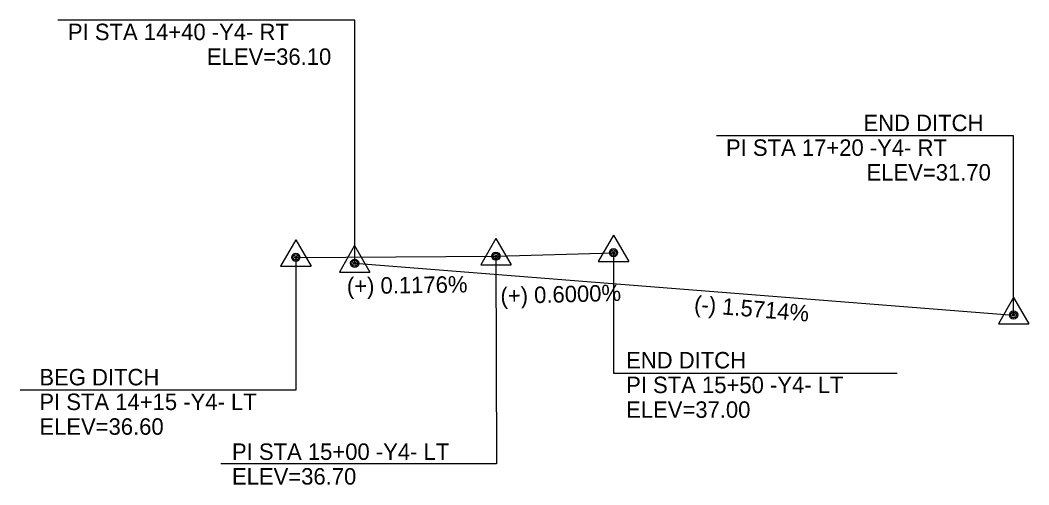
# Model space of a CAD drawing. Extents: x 2179808 to 2190174, y 63168 to 78602.
# Drawn here: x 2186905.5 to 2187334.2, y 75243.6 to 75441.1 of the extents above; entities that cross this region are included whole.
import ezdxf

# ---------------------------------------------------------------- set-up
doc = ezdxf.new("R2010")
doc.units = 0
for name, color, linetype in [('Default', 7, 'Continuous'), ('Prop Vertical Profile Ditch Grade Left', 7, 'Continuous'), ('Prop Vertical Profile Ditch Grade Left Label', 7, 'Continuous'), ('Prop Vertical Profile Ditch Grade Right', 7, 'Continuous'), ('Prop Vertical Profile Ditch Grade Right Label', 7, 'Continuous'), ('Prop VPI Ditch Grade Left Label', 7, 'Continuous'), ('Prop VPI Ditch Grade Right Label', 7, 'Continuous')]:
    doc.layers.add(name, color=color, linetype=linetype)

msp = doc.modelspace()

# ---------------------------------------------------------------- linework, layer by layer
at = {"layer": 'Default'}
for p, q in [((2187157.68, 75349.76), (2187151.23, 75338.56)), ((2187157.68, 75349.76), (2187164.18, 75338.56)), ((2187022.68, 75347.76), (2187016.23, 75336.56)), ((2187022.68, 75347.76), (2187029.18, 75336.56)), ((2187047.68, 75345.26), (2187041.23, 75334.06)), ((2187047.68, 75345.26), (2187054.18, 75334.06)), ((2187107.68, 75348.26), (2187101.23, 75337.06)), ((2187107.68, 75348.26), (2187114.18, 75337.06)), ((2187016.23, 75336.56), (2187029.18, 75336.56)), ((2187101.23, 75337.06), (2187114.18, 75337.06)), ((2187151.23, 75338.56), (2187164.18, 75338.56)), ((2187041.23, 75334.06), (2187054.18, 75334.06)), ((2187327.68, 75323.26), (2187321.23, 75312.06)), ((2187327.68, 75323.26), (2187334.18, 75312.06)), ((2187321.23, 75312.06), (2187334.18, 75312.06))]:
    msp.add_line(p, q, dxfattribs=at)
for centre, radius in [((2187022.69, 75340.28), 1.75), ((2187022.69, 75340.28), 1.2), ((2187107.69, 75340.78), 1.75), ((2187107.69, 75340.78), 1.2), ((2187157.69, 75342.28), 1.75), ((2187157.69, 75342.28), 1.2), ((2187047.69, 75337.78), 1.75), ((2187047.69, 75337.78), 1.2), ((2187327.69, 75315.78), 1.75), ((2187327.69, 75315.78), 1.2)]:
    msp.add_circle(centre, radius, dxfattribs=at)
at = {"layer": 'Prop Vertical Profile Ditch Grade Left'}
msp.add_lwpolyline([(2187022.69, 75340.28), (2187107.69, 75340.78), (2187157.69, 75342.28)], dxfattribs=at)
at = {"layer": 'Prop Vertical Profile Ditch Grade Right'}
msp.add_line((2187047.69, 75337.78), (2187327.69, 75315.78), dxfattribs=at)
at = {"layer": 'Prop VPI Ditch Grade Left Label'}
for points in [[(2187022.69, 75340.28), (2187022.69, 75283.87), (2186905.53, 75283.87)], [(2187107.69, 75340.78), (2187107.92, 75252.48), (2186990.76, 75252.48)], [(2187157.69, 75342.28), (2187157.69, 75291.08), (2187278.3, 75291.08)]]:
    msp.add_lwpolyline(points, dxfattribs=at)
for centre in [(2187022.69, 75340.28), (2187107.69, 75340.78), (2187157.69, 75342.28)]:
    msp.add_circle(centre, 0.5, dxfattribs=at)
at = {"layer": 'Prop VPI Ditch Grade Right Label'}
for points in [[(2187047.69, 75337.78), (2187047.69, 75441.12), (2186921.47, 75441.12)], [(2187327.69, 75315.78), (2187327.69, 75391.94), (2187201.47, 75391.94)]]:
    msp.add_lwpolyline(points, dxfattribs=at)
for centre in [(2187047.69, 75337.78), (2187327.69, 75315.78)]:
    msp.add_circle(centre, 0.5, dxfattribs=at)

# ---------------------------------------------------------------- texts
at = {"layer": 'Prop Vertical Profile Ditch Grade Left Label'}
for s, rotation, p in [('(+) 0.1176%', 0.8902, (2187044.41, 75324.61)), ('(+) 0.6000%', 1.5221, (2187109.73, 75320.43))]:
    msp.add_text(s, height=7, rotation=rotation, dxfattribs=at).set_placement(p)
at = {"layer": 'Prop Vertical Profile Ditch Grade Right Label'}
msp.add_text('(-) 1.5714%', height=7, rotation=355.1771, dxfattribs=at).set_placement((2187191.74, 75317.07))
at = {"layer": 'Prop VPI Ditch Grade Left Label'}
for s, p in [('END DITCH', (2187163.04, 75293.08)), ('BEG DITCH', (2186913.69, 75285.88)), ('PI STA 15+50 -Y4- LT', (2187163.04, 75282.58)), ('PI STA 14+15 -Y4- LT', (2186913.69, 75275.38)), ('ELEV=37.00', (2187163.04, 75272.08)), ('ELEV=36.60', (2186913.69, 75264.88)), ('PI STA 15+00 -Y4- LT', (2186995.54, 75254.19)), ('ELEV=36.70', (2186995.54, 75243.69))]:
    msp.add_text(s, height=7, dxfattribs=at).set_placement(p)
at = {"layer": 'Prop VPI Ditch Grade Right Label'}
for s, p in [('PI STA 14+40 -Y4- RT', (2186925.82, 75432.62)), ('ELEV=36.10', (2186984.9, 75422.12)), ('END DITCH', (2187263.9, 75393.94)), ('PI STA 17+20 -Y4- RT', (2187205.48, 75383.44)), ('ELEV=31.70', (2187265.22, 75372.94))]:
    msp.add_text(s, height=7, dxfattribs=at).set_placement(p)

doc.saveas('drawing.dxf')
